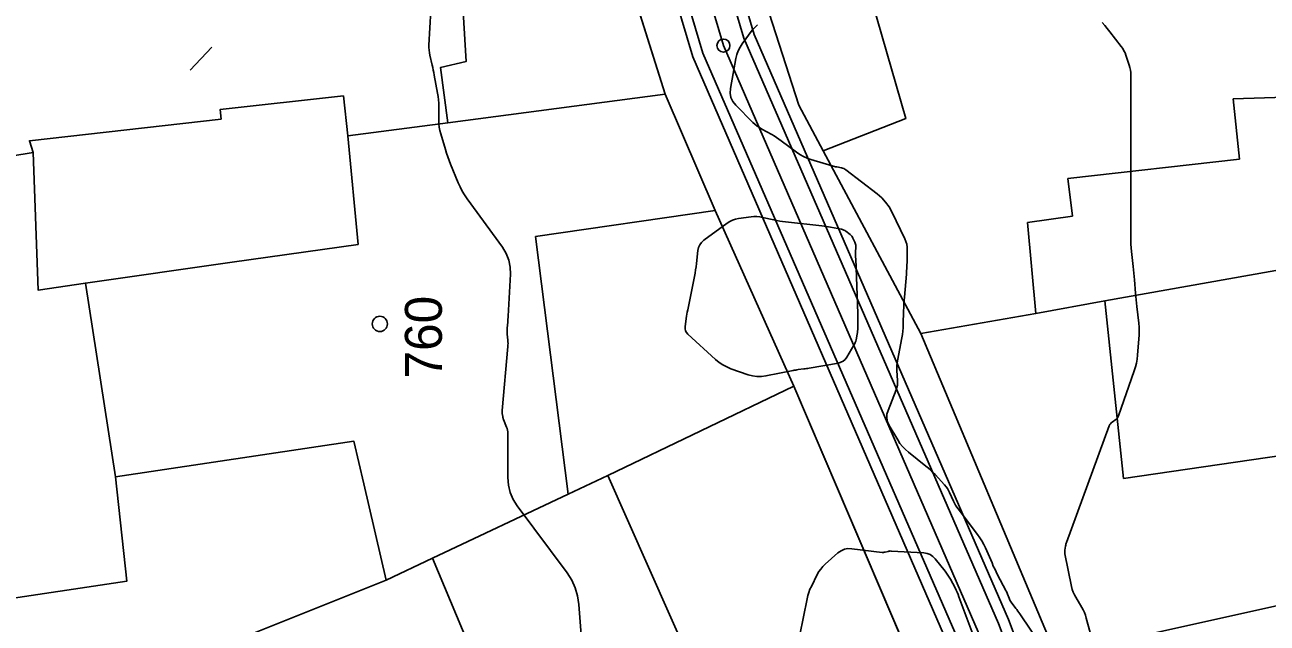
# Model space of a CAD drawing. Extents: x -534481 to -534256, y -1190577 to -1190138.
# Drawn here: x -534418.57 to -534390.01, y -1190477.55 to -1190463.81 of the extents above; entities that cross this region are included whole.
import ezdxf

# ---------------------------------------------------------------- set-up
doc = ezdxf.new("R2010")
doc.units = 0
for name, color, linetype in [('0_kroužky', 7, 'Continuous'), ('30', 7, 'Continuous'), ('31', 7, 'Continuous'), ('_N_osa', 7, 'Continuous'), ('_tenka', 7, 'Continuous'), ('Hranice parcel', 7, 'Continuous'), ('Parcelní čísla', 7, 'Continuous'), ('Polygon budovy', 7, 'Continuous'), ('Značky budov', 7, 'Continuous')]:
    doc.layers.add(name, color=color, linetype=linetype)

msp = doc.modelspace()

# ---------------------------------------------------------------- linework, layer by layer
at = {"layer": '0_kroužky'}
msp.add_circle((-534402.513, -1190464.283), 0.15, dxfattribs=at)
msp.add_circle((-534402.513, -1190464.283), 0.15, dxfattribs=at)
msp.add_circle((-534402.513, -1190464.283), 0.15, dxfattribs=at)
msp.add_circle((-534402.513, -1190464.283), 0.15, dxfattribs=at)
msp.add_circle((-534402.513, -1190464.283), 0.15, dxfattribs=at)
msp.add_circle((-534402.513, -1190464.283), 0.15, dxfattribs=at)
at = {"layer": '30'}
for points in [[(-534409.242, -1190463.48), (-534409.282, -1190464.272), (-534409.283, -1190464.33), (-534409.28, -1190464.388), (-534409.273, -1190464.446), (-534409.262, -1190464.503), (-534409.21, -1190464.731), (-534409.197, -1190464.788), (-534409.185, -1190464.845), (-534409.174, -1190464.902), (-534409.163, -1190464.959), (-534409.085, -1190465.377), (-534409.073, -1190465.454), (-534409.064, -1190465.531), (-534409.059, -1190465.609), (-534409.057, -1190465.688), (-534409.057, -1190466.001), (-534409.054, -1190466.079), (-534409.046, -1190466.157), (-534409.032, -1190466.233), (-534409.012, -1190466.309), (-534408.905, -1190466.673), (-534408.879, -1190466.758), (-534408.85, -1190466.843), (-534408.819, -1190466.927), (-534408.786, -1190467.01), (-534408.611, -1190467.435), (-534408.568, -1190467.531), (-534408.519, -1190467.625), (-534408.465, -1190467.716), (-534408.405, -1190467.803), (-534407.594, -1190468.918), (-534407.507, -1190469.061), (-534407.447, -1190469.212), (-534407.415, -1190469.371), (-534407.41, -1190469.539), (-534407.462, -1190470.498), (-534407.464, -1190470.533), (-534407.466, -1190470.567), (-534407.469, -1190470.602), (-534407.471, -1190470.637), (-534407.482, -1190470.775), (-534407.484, -1190470.81), (-534407.485, -1190470.844), (-534407.484, -1190470.879), (-534407.481, -1190470.914), (-534407.469, -1190471.055), (-534407.466, -1190471.09), (-534407.465, -1190471.125), (-534407.466, -1190471.161), (-534407.468, -1190471.196), (-534407.598, -1190472.667), (-534407.599, -1190472.685), (-534407.599, -1190472.702), (-534407.598, -1190472.72), (-534407.596, -1190472.738), (-534407.587, -1190472.809), (-534407.584, -1190472.827), (-534407.58, -1190472.844), (-534407.575, -1190472.861), (-534407.568, -1190472.878), (-534407.498, -1190473.05), (-534407.485, -1190473.084), (-534407.476, -1190473.12), (-534407.471, -1190473.156), (-534407.469, -1190473.192), (-534407.469, -1190474.208), (-534407.456, -1190474.385), (-534407.415, -1190474.553), (-534407.347, -1190474.712), (-534407.252, -1190474.862), (-534406.108, -1190476.396), (-534406, -1190476.564), (-534405.919, -1190476.742), (-534405.864, -1190476.93), (-534405.835, -1190477.127), (-534405.752, -1190478.22)], [(-534395.205, -1190478.07), (-534395.7, -1190477.339), (-534395.722, -1190477.307), (-534395.744, -1190477.275), (-534395.766, -1190477.244), (-534395.789, -1190477.214), (-534395.899, -1190477.069), (-534395.913, -1190477.049), (-534395.925, -1190477.028), (-534395.936, -1190477.006), (-534395.946, -1190476.983), (-534395.98, -1190476.891), (-534395.989, -1190476.868), (-534395.999, -1190476.845), (-534396.01, -1190476.823), (-534396.021, -1190476.801), (-534396.207, -1190476.444), (-534396.242, -1190476.377), (-534396.275, -1190476.309), (-534396.307, -1190476.241), (-534396.337, -1190476.172), (-534396.489, -1190475.823), (-534396.527, -1190475.744), (-534396.569, -1190475.666), (-534396.616, -1190475.592), (-534396.667, -1190475.52), (-534397.118, -1190474.929), (-534397.149, -1190474.886), (-534397.177, -1190474.841), (-534397.203, -1190474.795), (-534397.226, -1190474.748), (-534397.313, -1190474.554), (-534397.336, -1190474.507), (-534397.363, -1190474.462), (-534397.394, -1190474.42), (-534397.428, -1190474.379), (-534397.646, -1190474.141), (-534397.696, -1190474.089), (-534397.747, -1190474.04), (-534397.8, -1190473.992), (-534397.855, -1190473.947), (-534398.257, -1190473.629), (-534398.329, -1190473.567), (-534398.395, -1190473.498), (-534398.454, -1190473.424), (-534398.506, -1190473.344), (-534398.701, -1190473.011), (-534398.739, -1190472.927), (-534398.757, -1190472.841), (-534398.753, -1190472.754), (-534398.728, -1190472.665), (-534398.541, -1190472.194), (-534398.523, -1190472.141), (-534398.512, -1190472.087), (-534398.507, -1190472.031), (-534398.508, -1190471.975), (-534398.525, -1190471.749), (-534398.528, -1190471.692), (-534398.527, -1190471.636), (-534398.521, -1190471.58), (-534398.512, -1190471.524), (-534398.409, -1190470.997), (-534398.396, -1190470.921), (-534398.386, -1190470.844), (-534398.379, -1190470.766), (-534398.376, -1190470.689), (-534398.369, -1190470.377), (-534398.367, -1190470.3), (-534398.363, -1190470.222), (-534398.358, -1190470.144), (-534398.352, -1190470.067), (-534398.306, -1190469.533), (-534398.301, -1190469.464), (-534398.296, -1190469.395), (-534398.293, -1190469.327), (-534398.291, -1190469.258), (-534398.284, -1190468.982), (-534398.286, -1190468.914), (-534398.296, -1190468.848), (-534398.315, -1190468.783), (-534398.341, -1190468.72), (-534398.638, -1190468.106), (-534398.704, -1190467.987), (-534398.782, -1190467.879), (-534398.872, -1190467.781), (-534398.975, -1190467.692), (-534399.699, -1190467.135), (-534399.722, -1190467.12), (-534399.746, -1190467.108), (-534399.771, -1190467.098), (-534399.797, -1190467.092), (-534399.905, -1190467.071), (-534399.932, -1190467.066), (-534399.959, -1190467.059), (-534399.986, -1190467.053), (-534400.012, -1190467.045), (-534400.499, -1190466.899), (-534400.587, -1190466.868), (-534400.672, -1190466.83), (-534400.752, -1190466.785), (-534400.83, -1190466.732), (-534401.185, -1190466.468), (-534401.238, -1190466.43), (-534401.292, -1190466.394), (-534401.347, -1190466.36), (-534401.403, -1190466.328), (-534401.63, -1190466.202), (-534401.685, -1190466.168), (-534401.738, -1190466.131), (-534401.788, -1190466.091), (-534401.835, -1190466.047), (-534402.228, -1190465.653), (-534402.297, -1190465.569), (-534402.34, -1190465.476), (-534402.357, -1190465.375), (-534402.35, -1190465.267), (-534402.226, -1190464.581), (-534402.204, -1190464.49), (-534402.173, -1190464.404), (-534402.131, -1190464.321), (-534402.08, -1190464.243), (-534401.85, -1190463.932), (-534401.793, -1190463.865), (-534401.728, -1190463.806)]]:
    msp.add_lwpolyline(points, dxfattribs=at)
at = {"layer": '31'}
for points in [[(-534393.823, -1190478.7), (-534394.17, -1190477.437), (-534394.19, -1190477.373), (-534394.214, -1190477.311), (-534394.242, -1190477.25), (-534394.274, -1190477.191), (-534394.412, -1190476.96), (-534394.444, -1190476.901), (-534394.47, -1190476.84), (-534394.492, -1190476.778), (-534394.508, -1190476.713), (-534394.66, -1190475.962), (-534394.664, -1190475.94), (-534394.665, -1190475.918), (-534394.665, -1190475.896), (-534394.662, -1190475.874), (-534394.646, -1190475.785), (-534394.642, -1190475.762), (-534394.637, -1190475.741), (-534394.63, -1190475.719), (-534394.623, -1190475.698), (-534393.64, -1190473.017), (-534393.629, -1190472.993), (-534393.615, -1190472.971), (-534393.598, -1190472.952), (-534393.577, -1190472.936), (-534393.488, -1190472.875), (-534393.468, -1190472.858), (-534393.451, -1190472.839), (-534393.437, -1190472.818), (-534393.426, -1190472.794), (-534393.068, -1190471.755), (-534393.04, -1190471.667), (-534393.018, -1190471.578), (-534393.002, -1190471.488), (-534392.991, -1190471.396), (-534392.958, -1190471.025), (-534392.952, -1190470.935), (-534392.951, -1190470.845), (-534392.954, -1190470.755), (-534392.962, -1190470.665), (-534393.006, -1190470.277), (-534393.014, -1190470.201), (-534393.022, -1190470.125), (-534393.029, -1190470.048), (-534393.036, -1190469.972), (-534393.062, -1190469.666), (-534393.068, -1190469.59), (-534393.075, -1190469.513), (-534393.083, -1190469.437), (-534393.091, -1190469.361), (-534393.128, -1190469.012), (-534393.136, -1190468.928), (-534393.142, -1190468.844), (-534393.145, -1190468.76), (-534393.146, -1190468.676), (-534393.146, -1190464.963), (-534393.149, -1190464.904), (-534393.156, -1190464.846), (-534393.167, -1190464.789), (-534393.183, -1190464.732), (-534393.257, -1190464.507), (-534393.278, -1190464.452), (-534393.303, -1190464.4), (-534393.332, -1190464.35), (-534393.367, -1190464.302), (-534393.631, -1190463.964), (-534393.687, -1190463.892), (-534393.744, -1190463.821), (-534393.801, -1190463.75)], [(-534414.773, -1190464.845), (-534414.272, -1190464.316)], [(-534400.755, -1190477.821), (-534400.589, -1190476.994), (-534400.571, -1190476.92), (-534400.549, -1190476.848), (-534400.522, -1190476.777), (-534400.491, -1190476.709), (-534400.355, -1190476.437), (-534400.318, -1190476.371), (-534400.275, -1190476.31), (-534400.227, -1190476.253), (-534400.173, -1190476.2), (-534399.879, -1190475.941), (-534399.808, -1190475.89), (-534399.732, -1190475.856), (-534399.65, -1190475.841), (-534399.563, -1190475.843), (-534398.865, -1190475.927), (-534398.847, -1190475.928), (-534398.83, -1190475.928), (-534398.813, -1190475.926), (-534398.796, -1190475.922), (-534398.727, -1190475.904), (-534398.71, -1190475.9), (-534398.693, -1190475.898), (-534398.675, -1190475.896), (-534398.658, -1190475.897), (-534397.902, -1190475.941), (-534397.826, -1190475.953), (-534397.758, -1190475.979), (-534397.697, -1190476.02), (-534397.643, -1190476.074), (-534397.415, -1190476.358), (-534397.381, -1190476.402), (-534397.349, -1190476.448), (-534397.319, -1190476.496), (-534397.292, -1190476.545), (-534397.187, -1190476.745), (-534397.162, -1190476.795), (-534397.138, -1190476.846), (-534397.116, -1190476.898), (-534397.096, -1190476.95), (-534396.777, -1190477.804)]]:
    msp.add_lwpolyline(points, dxfattribs=at)
msp.add_lwpolyline([(-534401.64, -1190471.889), (-534401.741, -1190471.889), (-534401.842, -1190471.875), (-534401.941, -1190471.847), (-534402.338, -1190471.708), (-534402.435, -1190471.668), (-534402.526, -1190471.62), (-534402.611, -1190471.562), (-534402.692, -1190471.496), (-534403.332, -1190470.911), (-534403.363, -1190470.876), (-534403.383, -1190470.837), (-534403.393, -1190470.794), (-534403.392, -1190470.747), (-534403.366, -1190470.551), (-534403.359, -1190470.503), (-534403.351, -1190470.454), (-534403.342, -1190470.406), (-534403.333, -1190470.357), (-534403.178, -1190469.586), (-534403.164, -1190469.513), (-534403.151, -1190469.439), (-534403.14, -1190469.365), (-534403.131, -1190469.291), (-534403.097, -1190468.993), (-534403.082, -1190468.923), (-534403.054, -1190468.859), (-534403.013, -1190468.804), (-534402.959, -1190468.755), (-534402.426, -1190468.362), (-534402.367, -1190468.323), (-534402.304, -1190468.293), (-534402.238, -1190468.271), (-534402.169, -1190468.257), (-534401.876, -1190468.218), (-534401.81, -1190468.212), (-534401.744, -1190468.212), (-534401.678, -1190468.218), (-534401.612, -1190468.23), (-534401.35, -1190468.29), (-534401.284, -1190468.304), (-534401.218, -1190468.316), (-534401.152, -1190468.326), (-534401.085, -1190468.335), (-534400.251, -1190468.428), (-534400.199, -1190468.434), (-534400.148, -1190468.441), (-534400.098, -1190468.449), (-534400.047, -1190468.458), (-534399.801, -1190468.505), (-534399.773, -1190468.512), (-534399.746, -1190468.522), (-534399.721, -1190468.535), (-534399.697, -1190468.551), (-534399.598, -1190468.627), (-534399.579, -1190468.644), (-534399.562, -1190468.662), (-534399.547, -1190468.683), (-534399.535, -1190468.705), (-534399.49, -1190468.798), (-534399.48, -1190468.822), (-534399.473, -1190468.846), (-534399.469, -1190468.871), (-534399.468, -1190468.896), (-534399.472, -1190469.046), (-534399.473, -1190469.08), (-534399.473, -1190469.114), (-534399.472, -1190469.147), (-534399.471, -1190469.181), (-534399.421, -1190470.437), (-534399.419, -1190470.478), (-534399.419, -1190470.519), (-534399.419, -1190470.56), (-534399.419, -1190470.6), (-534399.423, -1190470.777), (-534399.424, -1190470.81), (-534399.427, -1190470.844), (-534399.432, -1190470.878), (-534399.438, -1190470.911), (-534399.464, -1190471.044), (-534399.471, -1190471.077), (-534399.482, -1190471.109), (-534399.495, -1190471.14), (-534399.512, -1190471.169), (-534399.676, -1190471.443), (-534399.714, -1190471.493), (-534399.758, -1190471.532), (-534399.811, -1190471.56), (-534399.87, -1190471.577), (-534400.544, -1190471.696), (-534400.575, -1190471.701), (-534400.605, -1190471.706), (-534400.636, -1190471.71), (-534400.667, -1190471.714), (-534400.79, -1190471.729), (-534400.821, -1190471.733), (-534400.851, -1190471.738), (-534400.882, -1190471.743), (-534400.912, -1190471.749), (-534401.537, -1190471.875)], close=True, dxfattribs=at)
at = {"layer": '_N_osa'}
msp.add_lwpolyline([(-534408.105, -1190518.46), (-534393.616, -1190502.389), (-534391.346, -1190496.962), (-534392.763, -1190488.017), (-534396.655, -1190477.752), (-534402.513, -1190464.283), (-534404.757, -1190456.741), (-534408.311, -1190433.088), (-534409.248, -1190427.879), (-534409.316, -1190416.054), (-534409.076, -1190409.418), (-534409.868, -1190391.439)], dxfattribs=at)
at = {"layer": '_tenka'}
for points in [[(-534405.407, -1190514.348), (-534394.258, -1190501.982), (-534392.12, -1190496.869), (-534393.492, -1190488.211), (-534397.35, -1190478.035), (-534403.219, -1190464.54), (-534405.491, -1190456.905), (-534409.051, -1190433.21), (-534409.998, -1190427.948), (-534410.066, -1190416.042), (-534409.827, -1190409.421), (-534410.645, -1190390.84)], [(-534405.057, -1190514.333), (-534394.044, -1190502.118), (-534391.862, -1190496.9), (-534393.249, -1190488.146), (-534397.118, -1190477.94), (-534402.983, -1190464.455), (-534405.247, -1190456.85), (-534408.804, -1190433.17), (-534409.748, -1190427.925), (-534409.816, -1190416.046), (-534409.577, -1190409.42), (-534410.397, -1190390.795)], [(-534403.656, -1190514.273), (-534393.187, -1190502.661), (-534390.83, -1190497.024), (-534392.278, -1190487.888), (-534396.191, -1190477.563), (-534402.042, -1190464.111), (-534404.268, -1190456.632), (-534407.818, -1190433.007), (-534408.749, -1190427.833), (-534408.816, -1190416.061), (-534408.576, -1190409.416), (-534409.363, -1190391.537)], [(-534403.306, -1190514.257), (-534392.973, -1190502.796), (-534390.572, -1190497.055), (-534392.035, -1190487.824), (-534395.96, -1190477.469), (-534401.807, -1190464.025), (-534404.023, -1190456.578), (-534407.571, -1190432.966), (-534408.499, -1190427.81), (-534408.566, -1190416.065), (-534408.326, -1190409.415), (-534409.111, -1190391.586)]]:
    msp.add_lwpolyline(points, dxfattribs=at)
at = {"layer": 'Hranice parcel'}
for p, q in [((-534403.85, -1190465.4), (-534406.36, -1190457.46)), ((-534397.97, -1190470.9), (-534394.87, -1190478.28)), ((-534395.25, -1190485.32), (-534400.89, -1190472.11))]:
    msp.add_line(p, q, dxfattribs=at)
for points in [[(-534403.02, -1190457.53), (-534401.68, -1190462.84), (-534400.78, -1190465.65), (-534400.22, -1190466.7), (-534397.97, -1190470.9)], [(-534427.58, -1190468.08), (-534423.54, -1190467.58), (-534422.92, -1190467.48), (-534418.38, -1190466.74), (-534418.47, -1190466.47), (-534414.06, -1190465.97), (-534414.08, -1190465.75), (-534411.25, -1190465.44), (-534411.15, -1190466.36)], [(-534411.15, -1190466.36), (-534408.85, -1190466.06), (-534403.85, -1190465.4)], [(-534400.89, -1190472.11), (-534402.7, -1190468.07), (-534403.85, -1190465.4)], [(-534416.49, -1190474.19), (-534417.18, -1190469.74), (-534413.81, -1190469.26), (-534410.91, -1190468.85), (-534411.15, -1190466.36)], [(-534381.52, -1190467.98), (-534393.74, -1190470.15), (-534395.33, -1190470.44), (-534397.97, -1190470.9)], [(-534427.58, -1190468.08), (-534427.04, -1190471.5), (-534426.32, -1190476.24), (-534422.32, -1190477.5), (-534416.23, -1190476.59), (-534416.49, -1190474.19)], [(-534410.27, -1190476.57), (-534409.2, -1190476.06), (-534406.08, -1190474.59), (-534405.17, -1190474.16), (-534400.89, -1190472.11)], [(-534416.49, -1190474.19), (-534411.01, -1190473.37), (-534410.78, -1190474.35), (-534410.27, -1190476.57)], [(-534394.87, -1190478.28), (-534389.45, -1190477.08), (-534382.56, -1190476.12), (-534376.75, -1190475.31)], [(-534410.27, -1190476.57), (-534413.98, -1190478.05), (-534410.74, -1190485.76)]]:
    msp.add_lwpolyline(points, dxfattribs=at)
at = {"layer": 'Polygon budovy'}
for points in [[(-534399.31, -1190462.53), (-534388.45, -1190461.56), (-534388.15, -1190465.42), (-534390.79, -1190465.51), (-534390.65, -1190466.89), (-534394.59, -1190467.34), (-534394.49, -1190468.2), (-534395.52, -1190468.35), (-534395.33, -1190470.44), (-534393.74, -1190470.15), (-534381.52, -1190467.98), (-534382.5, -1190455.87), (-534388.94, -1190456.35), (-534391.43, -1190456.53), (-534398.69, -1190457.05), (-534403.02, -1190457.53), (-534401.68, -1190462.84), (-534400.78, -1190465.65), (-534400.22, -1190466.7), (-534398.32, -1190465.96)], [(-534428.92, -1190459.94), (-534427.58, -1190468.08), (-534423.54, -1190467.58), (-534422.92, -1190467.48), (-534423.48, -1190463.44), (-534417.22, -1190462.74), (-534408.6, -1190461.72), (-534408.43, -1190464.65), (-534409.02, -1190464.79), (-534408.85, -1190466.06), (-534403.85, -1190465.4), (-534406.36, -1190457.46), (-534408.34, -1190457.68), (-534409.38, -1190457.79), (-534412.88, -1190458.18), (-534418.64, -1190458.82), (-534418.67, -1190458.67), (-534423.88, -1190459.32)], [(-534406.83, -1190468.67), (-534402.7, -1190468.07), (-534403.85, -1190465.4), (-534408.85, -1190466.06), (-534411.15, -1190466.36), (-534410.91, -1190468.85), (-534413.81, -1190469.26), (-534417.18, -1190469.74), (-534416.49, -1190474.19), (-534411.01, -1190473.37), (-534410.78, -1190474.35), (-534410.27, -1190476.57), (-534409.2, -1190476.06), (-534406.08, -1190474.59)], [(-534423.54, -1190467.58), (-534422.32, -1190477.5), (-534416.23, -1190476.59), (-534416.49, -1190474.19), (-534417.18, -1190469.74), (-534418.27, -1190469.9), (-534418.38, -1190466.74), (-534422.92, -1190467.48)], [(-534393.74, -1190470.15), (-534393.31, -1190474.23), (-534382.96, -1190472.72), (-534382.56, -1190476.12), (-534376.75, -1190475.31), (-534377.78, -1190467.51), (-534381.52, -1190467.98)], [(-534413.98, -1190478.05), (-534410.74, -1190485.76), (-534408.96, -1190490.21), (-534408.72, -1190490.82), (-534395.25, -1190485.32), (-534400.89, -1190472.11), (-534405.17, -1190474.16), (-534402.3, -1190480.62), (-534406.62, -1190482.23), (-534409.2, -1190476.06), (-534410.27, -1190476.57)]]:
    msp.add_lwpolyline(points, close=True, dxfattribs=at)
at = {"layer": 'Značky budov'}
msp.add_circle((-534410.411, -1190470.679), 0.175, dxfattribs=at)

# ---------------------------------------------------------------- texts
at = {"layer": 'Parcelní čísla'}
msp.add_text('760', height=0.85, rotation=90, dxfattribs=at).set_placement((-534408.985, -1190471.93))

doc.saveas('drawing.dxf')
